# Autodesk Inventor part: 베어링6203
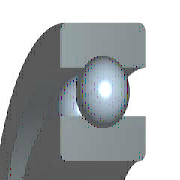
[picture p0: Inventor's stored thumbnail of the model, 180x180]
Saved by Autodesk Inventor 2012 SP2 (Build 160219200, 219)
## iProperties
IsCustomPart: 0
Company: 한국ATC센터
Created: 2014-12
Part Number: 베어링6203
Material: 강, 연강
Description: 깊은 그루브 볼 베어링
Document SubType Name: Modeling
Standard: KS B 2023
Designer: KYOUNG IL JANG
Standards Organization: KS
Language: ko-KR
Size Designation: 6203 - 17 x 40 x 12
Categories: <MemberInstance><Categories><Category DisplayName="샤프트 부품" InternalName="7f7aeb1f-a693-4053-b835-cee3144e0d98" Mnemonic="SHFT"><Category DisplayName="베어링" Inter
Density: 7.86 g/cm^3
Mass: 64.9809 g
Surface Area: 64.3582 cm^2
Volume: 8.26729 cm^3
Author: KYOUNG IL JANG
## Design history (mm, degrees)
revolve "본체" stored, may be unused: angle "d6" = 90 deg
revolve "볼" stored, may be unused: angle "d7" = 90 deg
pattern_circular "IDS_ARRAYBALL[SIMPL:T]" dims angle "d3" = 360 deg
body "Solid1"
sketch "스케치" dims "d0" = 5.98 (= -0.26 x WD + 0.26 x BD)
  geometry: L1 (3.01, 14.25)-(8.99, 14.25); L2 (6, 14.25)-(6, 11.26); L3 (6, 14.25)-(6, 17.24); L4 (3.778, 12.249)-(0, 12.249); L5 (0, 8.5)-(12, 8.5); L6 (3.778, 16.251)-(0, 16.251); L7 (0, 20)-(12, 20); L8 (12, 8.5)-(12, 12.249); L9 (8.222, 12.249)-(12, 12.249); L10 (8.222, 16.251)-(12, 16.251); L11 (12, 20)-(12, 16.251); L12 (-1.4, 0)-(8.4, 0) reference; L13 (0, -0.3)-(0, 5.3) reference
  constraints: 22 end point, 4 point on line, 2 collinear, 2 perpendicular, 2 symmetric about line, 1 midpoint, 1 parallel, 14 other
  dimensions: "d9" = 17 diameter of L5 L12 (= WD); "d11" = 40 diameter of L7 L12 (= BD); "d12" = 12 distance between parallel lines of L8 L13 (= KB); "d13" = 24.498 diameter of L9 L12 (= 0.326 x BD + 0.674 x WD)
fillet "모깎기1" dims "d1" = 0.6 (= KRS)
other parameters: "WD" = 17 [user parameter; used in 5 equation terms], "BD" = 40 [user parameter; used in 5 equation terms], "KB" = 12 [user parameter; used in 1 equation term], "KRS" = 0.6 [user parameter; used in 1 equation term], "d4" = 0, "d5" = 0, "d8" = 0, "d14" = 0, "d15" = 0, "BBA" = 0 [user parameter], "BC0" = 4750000 [user parameter], "BC" = 9560000 [user parameter], "WR" = 8.5 (= 0.5 x WD) [user parameter]
